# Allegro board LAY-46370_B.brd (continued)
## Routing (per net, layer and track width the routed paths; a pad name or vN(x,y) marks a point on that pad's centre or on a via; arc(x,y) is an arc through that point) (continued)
GND_CHASSIS:
  vias: v1(74.04,7.6) v1(74.04,6.33) v1(74.04,5.06) v1(74.04,3.79) v1(74.13,1.03) v1(75.44,0.95) v1(76.5,0.93) v1(77.77,0.93) v1(79.04,0.93) v1(80.31,0.93) v1(81.19,6.46) v1(81.19,5.19) v1(81.19,3.92) v1(81.19,2.65) v1(81.49,11.08) v1(81.49,9.81) v1(81.58,0.93) v1(82.46,6.46) v1(82.46,5.19) v1(82.46,3.92) v1(82.46,2.65) v1(82.76,11.08) v1(82.76,9.81) v1(82.85,0.93) v1(83.73,6.46) v1(83.73,5.19) v1(83.73,3.92) v1(83.73,2.65) v1(84.03,11.08) v1(84.03,9.81) v1(84.12,0.93) v1(85.39,0.93) v1(86.66,0.93) v1(87.93,0.93) v1(89.2,0.93) v1(90.47,0.93) v1(91.21,6.76) v1(91.21,5.49) v1(91.21,4.22) v1(91.21,2.95) v1(91.74,0.93) v1(92.48,6.76) v1(92.48,5.49) v1(92.48,4.22) v1(92.48,2.95) v1(93.01,0.93) v1(93.75,6.76) v1(93.75,5.49) v1(93.75,4.22) v1(93.75,2.95) v1(94.28,0.93) v1(95.55,0.93) v1(96.82,0.93) v1(98.09,0.93) v1(99.36,0.93) v1(100.44,4.71) v1(100.44,3.44) v1(100.44,2.17) v1(100.63,0.93) v1(101.79,4.68) v1(101.79,3.41) v1(101.79,2.14) v1(101.79,0.9) v1(102.06,10.86) v1(102.06,9.59) v1(102.06,8.32) v1(103.06,4.68) v1(103.06,3.41) v1(103.06,2.14) v1(103.06,0.9) v1(103.41,10.84) v1(103.41,9.57) v1(103.41,8.3) v1(104.33,0.9) v1(104.68,10.84) v1(104.68,9.57) v1(104.68,8.3) v1(105.6,0.9) v1(106.87,0.9) v1(107.06,10.4) v1(107.06,9.13) v1(108.14,0.9) v1(108.4,10.38) v1(108.4,9.11) v1(109.41,0.9) v1(110.68,0.9) v1(111.79,5.91) v1(111.79,3.88) v1(111.79,1.85) v1(112.91,10.65) v1(112.91,9.38) v1(112.91,8.11) v1(113.82,5.91) v1(113.82,3.88) v1(113.82,1.85) v1(114.26,10.62) v1(114.26,9.35) v1(114.26,8.08) v1(115.53,10.62) v1(115.53,9.35) v1(115.53,8.08) v1(115.85,5.91) v1(115.85,3.88) v1(115.85,1.85) v1(117.89,5.91) v1(117.89,3.88) v1(117.89,1.85) v1(119.92,5.91) v1(119.92,3.88) v1(119.92,1.85) v1(121.8,8.92) v1(121.8,7.65) v1(121.95,5.91) v1(121.95,3.88) v1(121.95,1.85) v1(123.14,8.89) v1(123.14,7.62) v1(123.98,5.91) v1(123.98,3.88) v1(123.98,1.85) v1(126.01,5.91) v1(126.01,3.88) v1(126.01,1.85) v1(128.05,5.91) v1(128.05,3.88) v1(128.05,1.85) v1(130.08,5.91) v1(130.08,3.88) v1(130.08,1.85) v1(132.11,5.91) v1(132.11,3.88) v1(132.11,1.85) v1(134.14,5.91) v1(134.14,3.88) v1(134.14,1.85) v1(136.17,5.91) v1(136.17,3.88) v1(136.17,1.85) v1(138.21,5.91) v1(138.21,3.88) v1(138.21,1.85) v1(140.24,5.91) v1(140.24,3.88) v1(140.24,1.85) v1(140.42,10.51) v1(140.42,9.24) v1(140.42,7.97) v1(141.36,10.51) v1(141.36,9.24) v1(141.36,7.97) v1(142.27,5.91) v1(142.27,3.88) v1(142.27,1.85) v1(144.3,5.91) v1(144.3,3.88) v1(144.3,1.85) v1(146.33,5.91) v1(146.33,3.88) v1(146.33,1.85) v1(146.9,10.89) v1(146.9,9.62) v1(146.9,8.35) v1(148.17,10.89) v1(148.17,9.62) v1(148.17,8.35) v1(148.37,5.91) v1(148.37,3.88) v1(148.37,1.85) v1(149.44,10.89) v1(149.44,9.62) v1(149.44,8.35) v1(150.4,5.91) v1(150.4,3.88) v1(150.4,1.85) v1(150.71,10.89) v1(150.71,9.62) v1(150.71,8.35) v1(151.85,5.93) v1(151.85,3.9) v1(151.85,1.87) v1(151.98,10.89) v1(151.98,9.62) v1(151.98,8.35) v1(153.25,10.89) v1(153.25,9.62) v1(153.25,8.35) v1(153.88,5.93) v1(153.88,3.9) v1(153.88,1.87) v1(154.52,10.89) v1(154.52,9.62) v1(154.52,8.35) v1(155.91,5.93) v1(155.91,3.9) v1(155.91,1.87) v1(157.95,5.93) v1(157.95,3.9) v1(157.95,1.87) v1(159.98,5.93) v1(159.98,3.9) v1(159.98,1.87) v1(160.75,7.65) v1(162.02,7.65) v1(162.01,5.93) v1(162.01,3.9) v1(162.01,1.87) v1(164.04,5.93) v1(164.04,3.9) v1(164.04,1.87) v1(166.07,5.93) v1(166.07,3.9) v1(166.07,1.87) v1(168.11,5.93) v1(168.11,3.9) v1(168.11,1.87) v1(170.14,5.93) v1(170.14,3.9) v1(170.14,1.87) v1(172.17,5.93) v1(172.17,3.9) v1(172.17,1.87) v1(174.2,5.93) v1(174.2,3.9) v1(174.2,1.87) v1(176.23,5.93) v1(176.23,3.9) v1(176.23,1.87) v1(178.27,5.93) v1(178.27,3.9) v1(178.27,1.87) v1(179.27,7.77) v1(180.3,5.93) v1(180.3,3.9) v1(180.3,1.87) v1(181.12,7.65) v1(182.33,5.93) v1(182.33,3.9) v1(182.33,1.87) v1(184.36,5.93) v1(184.36,3.9) v1(184.36,1.87) v1(185.35,7.65) v1(185.63,1.75) v1(185.66,10.41)
VBUS_IN:
  vias: v1(20.41,95.25) v1(20.39,93.95) v1(20.39,92.79) v1(21.49,95.25) v1(21.47,93.95) v1(21.47,92.8) v1(29.06,31.77) v1(29.07,31.13) v1(30.18,31.78) v1(30.19,31.14) v1(31.34,31.78) v1(31.35,31.14) v1(32.63,31.76) v1(32.64,31.11) v1(40.18,72.83) v1(40.16,71.54) v1(40.16,70.38) v1(41.38,72.79) v1(41.36,71.49) v1(41.36,70.33)
VBUS_USB_DBG: length 3.8
  TOP w0.381: v1(9.31,8.97) L15.2 v1(8.51,8.2)
  BOTTOM w0.381: C237.1 v1(5.11,10.61) ; C238.1 v1(2.78,10.63) ; C236.1 v1(3.95,10.64)
  vias: v1(28.1,58.96) v1(28.75,58.95)
VCC_3V6: length 10.1
  TOP w0.381: v1(40.5,62.64) 40.75,62.89 v1(47.35,62.89)
  BOTTOM w0.254: C263.1 v1(40.5,62.64) 41.46,63.61 U63.9
  BOTTOM w0.381: R258.1 v1(47.35,62.89)
VCC_FT_1V8: length 25.5
  TOP w0.254: U60.37 v1(14.77,26.15) ; U60.64 v1(8.32,17.7) ; U60.12 v1(14.77,16.74)
  TOP w0.381: L23.2 v1(4.86,35.01) ; R421.1 v1(36.17,65.18)
  BOTTOM w0.203: U7.11 13.43,50.64 12.9,51.18 C306.2
  BOTTOM w0.254: U70.21 8.08,68.82 C319.1 ; v1(19.56,72.23) 19.56,72.83 C335.1 20.26,72.84 20.32,72.78 U66.6 ; TP127.1 22.44,64.38 21.76,65.06 C327.1 21.28,65.07 U67.6
  BOTTOM w0.381: v1(8.07,67.06) C320.1 C319.1 ; C298.1 8.42,17.8 v1(8.32,17.7) ; R416.1 v1(16.96,65.84) ; C299.1 14.77,16.74 v1(14.77,16.74) ; L24.1 v1(6.73,26.01) ; v1(14.77,26.15) 14.79,26.14 C300.1 ; R419.1 v1(11.94,63.63) ; R420.1 v1(8.67,63.64) ; C327.1 v1(20.6,65.06) ; R415.1 v1(16.96,68.65) ; v1(14.6,51.8) C305.1 C306.2 ; R410.1 v1(19.92,69.91) ; R417.1 v1(16.93,64.24) ; R418.1 v1(13.02,63.6)
VCC_FT_3V3: length 44.1
  TOP w0.203: C330.1 14.47,36.27 U61.2
  TOP w0.254: U60.31 v1(17.73,24.7) ; U60.20 v1(17.73,19.2) ; U60.42 v1(12.27,26.15) ; U60.56 v1(8.32,21.7) ; U60.50 v1(8.32,24.7)
  TOP w0.381: R333.1 v1(22.41,21.39) ; R334.1 v1(22.38,22.99) ; L22.1 v1(11.17,11.91) ; U74.3 v1(6.04,28.78) ; R241.2 v1(5.25,25.69) ; R237.2 v1(10.33,34.09) ; v1(2.17,16.06) C239.1 v1(3.74,16.06) ; v1(4.79,28.07) C324.1 4.14,28.09 U74.1 ; v1(11.18,33.98) 11.48,33.68 R235.2 ; R242.2 v1(9.17,34.11) ; C330.1 C331.1 v1(14.55,34.46) ; L21.1 v1(14.89,12.84) ; R236.1 v1(3.84,19.44) ; R240.1 v1(3.85,18.3) ; R329.1 v1(16.83,12.47)
  TOP w0.508: C239.1 2.9,16.01 U59.5
  BOTTOM w0.254: C317.1 8.2,69.82 U70.23 ; C307.1 15.7,50.43 15.25,49.99 U7.1
  BOTTOM w0.381: R411.1 v1(8.06,74.61) ; v1(17.73,24.7) 17.72,24.68 C246.1 ; R413.1 v1(6.06,69.46) ; v1(17.73,19.2) 17.72,19.21 C244.1 ; TP126.1 25.64,47.68 v1(25.67,47.65) C338.1 26.9,48.11 U80.8 ; R440.2 v1(24.4,53.92) ; C317.1 C318.1 v1(8.04,71.66) ; C307.1 16.66,49.39 C308.2 v1(16.67,48.74) ; v1(8.32,24.7) 8.47,24.54 C297.1 9.02,24.52 C243.1 9.02,21.73 C296.1 8.34,21.72 v1(8.32,21.7) ; R385.1 v1(19.25,51.85) ; C245.1 12.29,26.13 v1(12.27,26.15)
VDD_1V8: length 111.5
  TOP w0.203: C55.1 49.26,18.93 49.12,18.8 U18.4 ; C328.1 15.14,36.67 U61.3 ; U4.3 118.13,30.71 C286.1
  TOP w0.254: v1(193.39,33.3) 193.21,33.12 U50.10 ; C228.1 181.91,77.6 U55.1 ; C217.1 137.15,38.14 U53.3 ; U50.8 194.84,31.82 v1(195.11,32.09) ; U79.6 163.85,130.39 C345.1
  TOP w0.305: v1(181.37,88.13) 181.65,87.85 U1.23 ; U57.1 181.75,59.95 C232.1 ; C230.1 181.96,95.65 U56.1 ; C234.1 181.78,51.53 U58.1 ; U2.6 178.32,90.69 C5.1 178.85,90.73 v1(178.9,90.77) ; C10.1 179.25,103.27 U5.1 ; 16.22,32.09 U78.6 ; U54.9 131.06,58.33 131.38,58.65 C336.1 ; U54.12 129.56,58.18 129.4,58.35 C337.1
  TOP w0.33: J13.A5 v1(88.85,133.56) ; J16.A5 v1(112.84,133.56) ; J15.A6 v1(136.04,133.56) ; J13.A6 v1(88.05,133.56) ; J14.A5 v1(40.86,133.56) ; J16.A6 v1(112.04,133.56) ; J15.A5 v1(136.84,133.56) ; J12.A5 v1(64.86,133.56) ; J14.A6 v1(40.06,133.56) ; J12.A6 v1(64.06,133.56)
  TOP w0.381: R226.1 v1(182.47,53.29) ; C228.1 v1(180.84,78.04) ; L10.1 v1(157.08,114.99) ; C10.1 v1(177.99,103.84) ; v1(161.14,124.63) R178.1 161.14,125.26 R177.1 ; TP123.1 87.37,115.48 v1(87.81,115.92) ; v1(14.71,40.11) 15.01,39.81 R429.1 ; R147.1 v1(167.25,112.27) ; R284.2 v1(6.36,136.33) ; U48.1 164.2,127.2 C168.1 163.84,128.66 C169.1 v1(163.84,129.4) ; 16.22,32.09 15.5,32.09 C346.1 15.5,32.53 v1(15.72,32.76) ; R312.1 v1(121.96,30.89) ; L9.2 v1(167.48,111.06) ; v1(175.49,102.82) 175.66,102.65 R7.1 176.2,102.62 R8.1 ; R130.1 v1(162.19,114.78) ; v1(136.69,39.49) C218.2 137.37,39.48 C217.1 ; C234.1 v1(180.73,51.94) ; v1(120.31,30.12) 120.11,30.32 C287.1 119.61,30.31 C286.1 ; C232.1 v1(180.35,60.71) ; v1(164.45,129.95) 163.95,130.46 C345.1 ; R244.1 v1(15.4,126.96) ; Q5.1 v1(163.83,134.02) ; R243.1 v1(15.41,125.86) ; R286.2 v1(9.31,136.33) ; v1(14.56,37.72) C329.1 C328.1 ; R283.2 v1(4.89,136.33) ; R224.1 v1(182.43,97.03) ; R15.1 v1(179.79,105.2) ; C55.1 C56.1 47.73,19.35 v1(47.47,19.62) ; R285.2 v1(7.83,136.33) ; R43.2 v1(24.23,26.2) ; R225.1 182.04,61.84 v1(182.39,62.19) ; R246.1 v1(24.09,127.95) ; R223.1 v1(182.58,79.41) ; TP132.1 v1(93.56,54.24) ; C230.1 v1(181.18,95.78) ; R70.1 v1(108.41,25.64) ; R431.1 v1(19.77,31.32) ; C337.1 v1(128.76,59.36) ; R101.1 v1(87.25,37.56) ; C336.1 v1(132.03,59.37) ; D22.A v1(12.62,128.89) ; R10.1 v1(176.2,98.73) ; R216.1 v1(136.53,42.24) ; R186.1 v1(165.75,131.05) ; R9.1 v1(175.59,100.47)
  BOTTOM w0.203: U20.14 11.97,78.37 11.98,78.38 C321.1 ; C309.1 8.04,50.58 U8.14
  BOTTOM w0.254: C12.1 109.61,94.42 U6.1 ; C37.1 111.57,85.28 U52.12 ; C33.1 109.84,85.46 110.07,85.22 U52.9
  BOTTOM w0.305: U3.1 C7.1
  BOTTOM w0.381: v1(114.13,98.12) 113.97,97.96 R19.1 ; C33.1 v1(109.1,86.25) ; R41.1 v1(127.84,84.3) ; v1(9.83,51.8) C310.2 C309.1 ; v1(131.92,82.95) C6.1 131.92,82.23 C7.1 ; v1(151.67,85.68) R422.2 R423.2 ; R18.1 v1(112.78,98.12) ; v1(193.39,33.3) 193.38,33.29 C185.1 C186.1 ; R16.1 v1(110.01,98.1) ; v1(12.76,76.68) C322.2 C321.1 ; C1.1 181.6,87.3 C2.1 181.61,87.89 v1(181.37,88.13) ; R27.1 v1(107.85,93.75) ; R313.2 v1(83.88,112.8) ; R4.1 v1(127.82,83.23) ; R17.1 v1(111.18,98.11) ; C184.1 195.02,32 v1(195.11,32.09) ; C12.1 v1(109.21,95.46) ; C37.1 v1(113.2,86.26)
  vias: v1(95.13,59.34) v1(95.13,58.73) v1(95.74,59.34) v1(95.74,58.73)
VDD_3V3: length 53.9
  TOP w0.203: U4.2 117.73,30.61 C289.1 ; U5.11 180.6,103.56 C11.1 ; C54.1 48.5,26.73 U17.3
  TOP w0.254: C30.1 35.5,18.32 U11.3 ; C219.1 136.97,37.74 U53.2
  TOP w0.305: v1(182.7,87.96) 182.65,87.91 U1.21 ; v1(68.17,31.9) 68.13,31.9 67.06,32.97 R48.1 ; R448.1 v1(56.68,26.48)
  TOP w0.381: C289.1 116.33,30.31 C288.1 v1(116.32,30.91) ; R113.2 88.18,23.71 v1(87.94,23.94) ; v1(48.27,25.67) 48.62,26.02 C54.1 ; v1(93.6,37.54) 93.6,36.82 L1.1 93.73,36.91 R84.2 ; R447.2 27.93,18.2 v1(27.76,18.37) ; R212.1 v1(139.3,23.48) ; v1(79.63,22.58) 79.92,22.88 L6.1 ; v1(169.75,131.66) D9.A 170.57,132.62 v1(170.54,132.65) ; R14.1 v1(183.62,99.35) ; C11.1 v1(181.52,103.84) ; L14.1 v1(199.28,22.68) ; C30.1 35.44,18.87 v1(34.87,18.87) ; v1(82.32,114.3) 82.18,114.17 R66.1 ; R60.1 v1(39.83,28.04) ; L5.1 v1(75.33,36.98) ; R68.1 v1(58.9,26.46) ; R426.1 v1(131.2,23.48) ; R12.1 v1(183.64,101.51) ; U51.11 134.6,24.93 v1(134.64,24.89) ; R11.1 v1(183.67,102.57) ; TP131.1 v1(90.19,54.24) ; R83.2 v1(107.76,25.16) ; R270.1 v1(4.2,140.76) ; R129.1 v1(163.9,114.18) ; v1(136.78,36.24) C220.2 137.37,36.25 C219.1 ; L2.1 v1(98.5,23) ; R114.2 v1(74.85,35.19) ; R13.1 v1(183.6,100.43)
  BOTTOM w0.254: U6.11 109.64,93.07 C13.1 ; C9.1 136.68,83.93 U3.23 ; R20.1 v1(109.94,90.02)
  BOTTOM w0.305: U3.24 134.49,82.49 C8.1
  BOTTOM w0.381: R269.1 45.59,107.03 v1(45.95,106.66) ; C204.1 135.1,25.67 C205.1 135.11,25.36 v1(134.64,24.89) ; C8.1 v1(135.45,82.23) ; v1(136.53,83.19) 136.78,83.45 C9.1 ; R282.1 v1(17.92,99.45) ; R23.1 v1(114.62,90.64) ; R22.1 v1(111.96,90.64) 111.96,90.64 R21.1 ; C13.1 v1(109.22,92.01) ; C4.1 183.77,87.28 C3.1 v1(182.7,87.96) ; R264.1 v1(50.72,101.8)
  vias: v1(95.28,64.71) v1(95.29,64.1) v1(95.89,64.71) v1(95.9,64.1)
VDD_3V3_CN: length 1.7
  TOP w0.254: D9.C 170.51,134.14
  TOP w0.381: 170.51,134.14 R174.1
VDD_5V: length 90.9
  TOP w0.203: U17.12 42.29,26.33 C57.2 ; U11.12 29.98,17.92 C31.2
  TOP w0.33: J12.A16 v1(56.06,133.56) ; J13.A16 v1(80.05,133.56) ; J16.A17 v1(103.24,133.56) ; J15.A16 v1(128.04,133.56) ; J12.A17 v1(55.26,133.56) ; J14.A16 v1(32.06,133.56) ; J16.A16 v1(104.04,133.56) ; J15.A17 v1(127.24,133.56) ; J13.A17 v1(79.25,133.56) ; J14.A17 v1(31.26,133.56)
  TOP w0.381: R204.1 v1(182.11,21.02) ; R46.1 v1(71.08,40.15) ; U51.3 135.87,32.47 v1(136.18,32.78) ; v1(181.72,126.45) 176.59,126.45 176.33,126.19 R455.1 176.06,125.27 Q16.2 ; v1(185.34,21.41) Q6.2 v1(184.52,20.67) ; C197.1 v1(183.23,21.02) ; C31.2 29.28,16.98 29.81,16.98 v1(29.98,17.14) ; C57.2 v1(42.21,25.59)
  L6_IN2 w0.381: v1(42.21,25.59) 33.64,25.59 30.37,22.31 30.37,17.53 v1(29.98,17.14)
  BOTTOM w0.381: v1(136.18,32.78) 136.5,32.46 C202.1 135.41,32.13 C203.1 ; v1(73.77,37.64) 69.15,33.02 69.15,30.23 63.5,24.58 56.86,24.58 55.39,23.12 45.56,23.12 43.1,25.59 v1(42.21,25.59)
  vias: v1(55.45,103.16) v1(55.46,104.44) v1(55.47,103.81) v1(56.2,104.47) v1(56.21,103.84) v1(56.22,103.17) v1(68.27,40.01) v1(68.26,39.37) v1(195.65,109.24) v1(195.65,108.61) v1(195.66,107.95) v1(197.97,109.14) v1(197.98,108.51) v1(197.99,107.85) v1(199.99,106.73) v1(200,106.1) v1(200.01,105.45)
1GB_LINK/ACTIVE: length 20.2
  TOP w0.254: R78.1 95.45,19.19 95.45,13.24 99.43,9.25 99.43,6.17 J8.11
10M_100M_LINK/ACTIVE: length 18.5
  TOP w0.254: R74.1 108.18,14.81 107,13.64 107,12.53 105.59,11.11 105.59,3.64 J8.13
AUD_3V3: length 8.2
  TOP w0.305: L14.2 199.15,24.26 R187.1 197.8,24.57 C189.1 196.49,24.26 C190.1 195.53,25.59 193.71,27.4 U50.32
AUD_5V: length 7.1
  TOP w0.203: U50.26 v1(190.71,26.94) ; v1(188.65,29.78) 188.69,29.82 U50.21
  TOP w0.381: v1(187.33,22.06) Q6.3 185.95,22.53 C15.1
  BOTTOM w0.381: v1(188.65,29.78) 188.75,29.68 C188.1
  BOTTOM w0.508: v1(190.71,26.94) 190.43,27.22 C187.1
AUD_NINT: length 95.2
  TOP w0.102: v1(112,66.94) 112.03,66.94 112.09,67 J4.26
  TOP w0.109: v1(191.12,37.61) 190.17,36.66 R188.1
  BOTTOM w0.109: v1(191.12,37.61) 190.93,37.61 182.57,45.96 148.15,45.96 127.47,66.65 112.27,66.65 112,66.92 v1(112,66.94)
AUD_PWR_EN: length 114.3
  TOP w0.102: J4.24 112.27,66.6 112.17,66.51 111.76,66.51 110.89,67.38 v1(110.89,67.94)
  TOP w0.203: R207.1 v1(186.49,20.13)
  L6_IN2 w0.114: v1(186.49,20.13) v1(186.49,45.33)
  BOTTOM w0.109: v1(110.89,67.94) 110.89,68.06 111.25,68.42 127.95,68.42 149.02,47.35 184.46,47.35 v1(186.49,45.33)
AUD_SCL: length 2.9
  TOP w0.203: U50.17 189.18,31.82 188.9,32.1 187.77,32.1 R198.2
AUD_SDA: length 2.6
  TOP w0.203: U50.18 189.12,31.32 188.74,31.71 R197.2
BOOT_MODE0: length 88.6
  TOP w0.109: v1(10.24,76.59) 8.12,76.59 7.06,77.64 7.06,79.54 9.99,82.46 55.95,82.46 71.39,97.89 71.39,105.49 72.69,106.79 J1.9
  BOTTOM w0.109: v1(10.24,76.59) 9.97,76.86 U20.2
BOOT_MODE1: length 86
  TOP w0.109: v1(8.56,77.03) 8.11,77.03 7.34,77.81 7.34,79.31 10.2,82.18 56.15,82.18 72.03,98.07 72.03,105.8 73.09,106.86 J1.11
  BOTTOM w0.109: U20.5 v1(8.56,77.03)
BOOT_MODE2: length 83.9
  TOP w0.109: v1(7.84,78.73) 7.84,79.36 10.26,81.78 56.33,81.78 72.62,98.07 72.62,106.05 73.36,106.8 73.36,107.09 73.49,107.22 J1.13
  BOTTOM w0.109: v1(7.84,78.73) 8.2,78.37 U20.7
BOOT_MODE3: length 82.1
  TOP w0.109: v1(10.02,80.62) 10.78,81.38 56.44,81.38 72.86,97.79 72.86,105.96 73.6,106.7 73.6,106.91 73.89,107.2 J1.15
  BOTTOM w0.109: U20.10 9.57,79.49 9.5,79.56 9.5,80.11 v1(10.02,80.62)
BYPASS: length 2.3
  TOP w0.109: C29.2 35.15,19.84 34.03,18.72 U11.4
BYPASS1: length 1.4
  TOP w0.203: U17.4 46.97,27.13 C51.2
CAN1/I2C5_SEL: length 81.4
  TOP w0.109: v1(129.7,81.21) 130.01,81.52 156.4,81.52 159.6,84.71 178.89,84.71 179.16,84.98 R444.1 179.34,85.47 U1.3
  L6_IN2 w0.114: v1(108.51,84.9) 109.2,85.58 v1(110.45,85.58)
  BOTTOM w0.102: U52.10 110.57,85.48 110.47,85.58 v1(110.45,85.58) ; U52.7 109.06,84.9 v1(108.51,84.9)
  BOTTOM w0.109: v1(108.51,84.9) 108.14,84.52 108.14,82.79 110.02,80.91 121.78,80.91 122.64,81.78 129.13,81.78 v1(129.7,81.21)
CAN1_H: length 14
  TOP w0.254: J19.7 132.88,12.73 134,13.85 D14.2 134.19,17.16 L19.2 132.66,19 C206.2 131.32,18.98 R210.1
CAN1_L: length 11.7
  TOP w0.254: R211.1 138.58,18.99 C208.1 137.2,19 L19.3 135.64,17.21 D14.1 136.22,16.63 136.22,13.25 J19.2
CAN1_RX: length 70.4
  TOP w0.109: U53.8 133.3,39.15 132.01,40.44 v1(132.01,40.56) 132.01,41.4 TP108.1
  L6_IN2 w0.114: v1(129.69,81.85) 133.21,78.32 133.21,41.76 v1(132.01,40.56)
  BOTTOM w0.109: U52.5 109.57,83.21 109.33,82.97 109.33,82.03 110.06,81.3 121.49,81.3 122.3,82.11 129.43,82.11 v1(129.69,81.85)
CAN1_RX_3V3: length 5.4
  TOP w0.254: U51.4 v1(134.6,32.72) ; U53.13 134.34,36.2 v1(134.13,35.98)
  L6_IN2 w0.254: v1(134.13,35.98) 134.13,33.2 v1(134.6,32.72)
CAN1_STBY_3V3: length 66.6
  TOP w0.109: R212.2 138.41,24.48 U51.14 v1(138.41,27.37)
  L6_IN2 w0.114: v1(137.17,88.39) 137.17,86.62 138.21,85.58 138.21,27.58 v1(138.41,27.37)
  BOTTOM w0.102: U3.15 136.71,87.93 v1(137.17,88.39)
CAN1_TX: length 66.7
  TOP w0.102: U53.6 135.14,39.84 v1(134.8,40.19)
  TOP w0.109: TP106.1 133.88,41.1 v1(134.8,40.19)
  L6_IN2 w0.114: v1(134.8,40.19) 133.51,41.47 133.51,78.65 129.67,82.5 v1(129.65,82.5)
  BOTTOM w0.109: v1(129.65,82.5) 121.47,82.5 120.55,83.41 111.55,83.41 111.07,83.89 U52.2
CAN1_TX_3V3: length 6.5
  TOP w0.254: U51.1 138.41,32.13 135.14,35.4 U53.15
CAN1H: length 8.5
  TOP w0.254: U51.13 137.14,21.84 136.32,21.01 134.45,21.01 134.19,21.28 L19.1
CAN1L: length 4.2
  TOP w0.254: L19.4 135.87,22.28 U51.12
CAN2_H: length 18.3
  TOP w0.254: R214.1 162.21,20.08 C214.2 163.59,20.1 L20.2 165.15,18.22 D15.2 165.01,15.29 166.38,13.92 167.23,13.92 169.16,11.98 169.16,10.74 171.46,8.44 J20.7
CAN2_L: length 15.3
  TOP w0.254: J20.2 171.74,12.85 170.36,12.85 166.89,16.32 D15.1 166.89,18.75 166.6,19.03 L20.3 168.14,20.1 C216.1 169.53,20.11 R215.1
CAN2_RX: length 36.6
  TOP w0.109: U53.9 131.06,38.54 TP109.1 112.02,57.58 112.02,63.03 112.39,63.41 J4.8
CAN2_RX_3V3: length 7.5
  TOP w0.254: U51.7 130.79,34.3 133.84,37.34 U53.12
CAN2_STBY_3V3: length 68.7
  TOP w0.109: R426.2 130.79,24.53 U51.8 v1(130.79,27.62)
  L6_IN2 w0.114: v1(130.79,27.62) 130.79,28.23 137.81,35.24 137.81,85.48 136.49,86.8 v1(136.49,88.43)
  BOTTOM w0.102: U3.14 v1(136.49,88.43)
CAN2_TX: length 25.3
  TOP w0.102: v1(130.27,58.7) 130.06,58.5 U54.11
  TOP w0.109: U53.7 134.74,39.54 132.96,41.32 132.96,42.09 v1(132.66,42.39) 131.03,42.39 TP107.1
  L6_IN2 w0.127: v1(132.66,42.39) 130.27,44.78 v1(130.27,58.7)
CAN2_TX_3V3: length 6.2
  TOP w0.254: U53.14 134.74,35.2 132.06,32.52 U51.6
CAN2H: length 38.4
  TOP w0.254: L20.1 165.6,23.59 165.6,26.36 163.91,28.04 133.52,28.04 132.99,27.51 132.99,26.97 133.33,26.62 U51.10
CAN2L: length 40.3
  TOP w0.254: U51.9 132.06,26.61 132.43,26.97 132.43,27.74 133.29,28.6 164.15,28.6 166.16,26.59 166.16,23.59 L20.4
CLK_PD#: length 3.2
  TOP w0.109: U29.22 160.2,106.43 TP128.1
CLKIN1: length 7.3
  TOP w0.102: TP1.1 110.43,116.55 112.1,114.89 112.1,113.26 111.26,112.43 111.26,111.42 111.53,111.15 J2.86
CLKIN2: length 6
  TOP w0.102: TP3.1 113.21,116.49 113.21,111.06 113.13,110.98 J2.94
CLKOUT1: length 6.4
  TOP w0.102: J2.90 112.33,111.16 112.23,111.27 112.23,111.92 112.53,112.23 112.53,115.77 TP2.1
CLKOUT2: length 6.3
  TOP w0.102: TP4.1 114.08,115.84 114.08,111.22 113.93,111.07 J2.98
CON_JTAG_TCK: length 87.1
  L6_IN2 w0.114: J24.4 17.79,128.58 17.21,128.01 17.21,100.51 5.14,88.44 5.14,54.81 v1(9.31,50.64)
  BOTTOM w0.109: U8.16 9.25,50.58 v1(9.31,50.64)
CON_JTAG_TDI: length 105
  TOP w0.109: J24.8 17.94,131.12 17.53,130.71 17.53,127.73 R244.2
  L6_IN2 w0.114: J24.8 17.02,131.12 16.29,130.39 16.29,100.9 4.47,89.07 4.47,49.84 6.77,47.53 7.77,47.53 9.78,49.53 10.16,49.53 v1(10.59,49.97)
  BOTTOM w0.109: U8.3 9.79,49.17 v1(10.59,49.97)
CON_JTAG_TDO: length 88.9
  L6_IN2 w0.114: J24.6 17.26,129.85 16.77,129.36 16.77,100.7 4.77,88.7 4.77,51.71 v1(6.51,49.97)
  BOTTOM w0.109: U8.12 v1(6.51,49.97)
CON_JTAG_TMS: length 93.6
  TOP w0.109: J24.2 18.23,127.31 R243.2
  L6_IN2 w0.114: J24.2 18.31,127.31 17.53,126.53 17.53,100.38 5.44,88.3 5.44,57.88 10.32,53 10.32,51.01 7.28,47.98 v1(7.08,47.98)
  BOTTOM w0.109: v1(7.08,47.98) 7.08,48.67 7.18,48.77 U8.9
CSI1_CKN: length 52.4
  TOP w0.091: J1.84 87.5,110.66 87.5,111.2 87.56,111.26 87.56,111.86 88.28,112.58 v1(88.28,112.58) ; J12.A2 67.26,133.05 66.99,133.31 66.99,133.69 67.08,133.78 68.36,133.78 69.95,132.19 69.95,127.09 69.86,126.99 U31.10 U31.1 69.86,125.07 69.97,124.95 69.97,124.45 69.81,124.29 v1(69.81,124.22)
  L3_IN1 w0.084: v1(69.81,124.22) 69.97,124.38 69.97,124.75 70.22,124.99 72.52,124.99 73.07,124.45 73.07,122.1 72.82,121.86 70.65,121.86 70.57,121.77 70.57,121.27 70.65,121.18 72.52,121.18 72.87,120.82 72.87,120.36 72.53,120.02 70.65,120.02 70.57,119.93 70.57,119.3 70.74,119.13 82.69,119.13 87.83,113.99 87.83,112.67 87.92,112.58 v1(88.28,112.58)
CSI1_CKP: length 52.5
  TOP w0.091: v1(88.3,112) 88.07,112 87.83,111.75 87.83,111.26 87.9,111.2 87.9,110.66 J1.86 ; v1(70.4,124.22) 70.4,124.29 70.24,124.45 70.24,124.95 70.36,125.07 U31.2 U31.9 70.36,127.01 70.22,127.15 70.22,132.3 68.48,134.05 66.97,134.05 66.72,133.8 66.72,133.32 66.46,133.05 J12.A3
  L3_IN1 w0.084: v1(70.4,124.22) 70.24,124.38 70.24,124.64 70.33,124.73 72.41,124.73 72.8,124.34 72.8,122.21 72.71,122.13 70.54,122.13 70.3,121.88 70.3,121.16 70.54,120.91 72.41,120.91 72.6,120.71 72.6,120.47 72.42,120.29 70.54,120.29 70.3,120.04 70.3,119.19 70.63,118.86 82.58,118.86 87.56,113.88 87.56,112.56 87.81,112.31 87.94,112.31 88.26,112 v1(88.3,112)
CSI1_DN0: length 51.6
  TOP w0.091: v1(85.87,112.6) 85.82,112.6 85.16,111.93 85.16,111.1 85.1,111.03 85.1,110.66 J1.72 ; J12.B2 67.66,128.92 67.39,128.65 67.39,128.14 66.65,127.4 66.65,127.2 66.77,127.09 U32.1 U32.10 66.77,125.07 66.65,124.95 66.65,122.8 v1(66.81,122.64)
  L3_IN1 w0.084: v1(66.81,122.64) 66.65,122.48 66.65,121.56 66.4,121.31 64.18,121.31 64.1,121.23 64.1,121.05 64.18,120.96 66.4,120.96 66.65,120.71 66.65,120.31 66.4,120.07 64.18,120.07 64.1,119.98 64.1,119.8 64.18,119.71 66.4,119.71 66.65,119.47 66.65,119.07 66.4,118.83 64.18,118.83 64.1,118.74 64.1,118.56 64.18,118.47 66.4,118.47 66.65,118.22 66.65,116.66 67.34,115.97 83.04,115.97 85.46,113.54 85.46,112.74 85.67,112.53 85.8,112.53 v1(85.87,112.6)
CSI1_DN1: length 51.3
  TOP w0.091: J12.B5 65.26,128.87 64.99,128.6 64.99,127.94 65.14,127.79 65.14,127.21 65.27,127.09 U32.4 U32.7 65.27,125.07 65.15,124.95 65.15,124.68 v1(65.32,124.5) ; J1.78 86.3,110.66 86.3,111.2 86.36,111.26 86.36,111.87 87.02,112.53 87.04,112.53 v1(87.07,112.56)
  L3_IN1 w0.084: v1(65.32,124.5) 65.16,124.34 65.16,124.08 65.57,123.68 67.47,123.68 68.83,122.32 68.83,117.84 69.67,117 70.49,117 70.57,117.08 70.57,117.55 70.82,117.79 71.22,117.79 71.46,117.55 71.46,117.08 71.55,117 71.73,117 71.82,117.08 71.82,117.68 72.06,117.93 72.46,117.93 72.71,117.68 72.71,117.08 72.8,117 72.97,117 73.06,117.08 73.06,117.68 73.31,117.93 73.71,117.93 73.95,117.68 73.95,117.08 74.04,117 74.22,117 74.31,117.08 74.31,117.68 74.55,117.93 74.95,117.93 75.2,117.68 75.2,117.08 75.29,117 75.46,117 75.55,117.08 75.55,117.68 75.8,117.93 76.2,117.93 76.44,117.68 76.44,117.08 76.53,117 76.71,117 76.8,117.08 76.8,117.68 77.04,117.93 77.44,117.93 77.69,117.68 77.69,117.08 77.78,117 77.95,117 78.04,117.08 78.04,117.68 78.29,117.93 78.69,117.93 78.93,117.68 78.93,117.08 79.02,117 79.2,117 79.29,117.08 79.29,117.68 79.53,117.93 79.93,117.93 80.18,117.68 80.18,117.08 80.26,117 80.44,117 80.53,117.08 80.53,117.68 80.78,117.93 81.17,117.93 81.42,117.68 81.42,117.08 81.51,117 83.44,117 86.61,113.83 86.61,112.73 86.78,112.56 v1(87.07,112.56)
CSI1_DN2: length 51.2
  TOP w0.091: v1(89.47,112.58) 89.47,112.58 88.76,111.87 88.76,111.26 88.7,111.2 88.7,110.66 J1.90 ; v1(58.14,124.47) 58.02,124.59 58.02,125 58.14,125.11 U33.10 U33.1 58.14,127.09 58.02,127.2 58.02,127.4 58.59,127.97 58.59,128.62 58.86,128.89 J12.B13
  L3_IN1 w0.084: v1(58.14,124.47) 57.94,124.28 57.94,123.98 58.21,123.72 58.45,123.72 58.69,123.47 58.69,122.69 58.78,122.6 58.96,122.6 59.05,122.69 59.05,123.47 59.29,123.72 59.69,123.72 59.94,123.47 59.94,122.69 60.03,122.6 60.2,122.6 60.29,122.69 60.29,123.47 60.54,123.72 61.58,123.72 63.77,125.9 73.14,125.9 78.86,120.18 82.88,120.18 89.03,114.03 89.03,112.67 89.12,112.58 v1(89.47,112.58)
CSI1_DN3: length 51.2
  TOP w0.091: J12.B16 56.46,129.15 56.18,128.87 56.18,128.25 56.52,127.9 56.52,126.94 56.64,126.82 U33.4 U33.7 56.64,125.3 56.5,125.16 56.5,124.71 v1(56.66,124.54) ; J1.96 89.89,110.95 89.99,111.05 89.99,111.66 90.29,111.96 90.29,112.23 90.23,112.29 90.15,112.29 90.07,112.37 90.07,112.52 90.16,112.61 v1(90.7,112.61)
  L3_IN1 w0.084: v1(90.7,112.61) 90.94,112.61 91.12,112.78 91.12,113.37 83.65,120.84 79.34,120.84 73.65,126.52 57.55,126.52 56.35,125.32 56.35,124.88 56.66,124.56 v1(56.66,124.54)
CSI1_DP0: length 51.6
  TOP w0.091: v1(66.22,122.64) 66.38,122.8 66.38,124.95 66.27,125.07 U32.9 U32.2 66.27,127.09 66.38,127.2 66.38,127.51 67.12,128.25 67.12,128.66 66.86,128.92 J12.B3 ; v1(85.88,112.01) 85.68,112.01 85.44,111.78 85.44,111.25 85.5,111.2 85.5,110.66 J1.74
  L3_IN1 w0.084: v1(66.22,122.64) 66.38,122.48 66.38,121.67 66.29,121.58 64.07,121.58 63.83,121.34 63.83,120.94 64.07,120.69 66.29,120.69 66.38,120.6 66.38,120.43 66.29,120.34 64.07,120.34 63.83,120.09 63.83,119.69 64.07,119.45 66.29,119.45 66.38,119.36 66.38,119.18 66.29,119.09 64.07,119.09 63.83,118.85 63.83,118.45 64.07,118.2 66.29,118.2 66.38,118.11 66.38,116.55 67.23,115.7 82.93,115.7 85.19,113.43 85.19,112.63 85.81,112.01 v1(85.88,112.01)
CSI1_DP1: length 51.2
  TOP w0.091: J1.80 86.7,110.66 86.7,111.2 86.63,111.26 86.63,111.69 86.91,111.98 v1(87.08,111.98) ; J12.B6 64.46,128.85 64.72,128.58 64.72,127.83 64.88,127.68 64.88,127.2 64.77,127.09 U32.5 U32.6 64.77,125.07 64.88,124.95 64.88,124.65 v1(64.74,124.5)
  L3_IN1 w0.084: v1(64.74,124.5) 64.9,124.34 64.9,123.97 65.46,123.41 67.36,123.41 68.56,122.21 68.56,117.73 69.56,116.73 70.6,116.73 70.84,116.97 70.84,117.44 70.93,117.53 71.11,117.53 71.2,117.44 71.2,116.97 71.44,116.73 71.84,116.73 72.09,116.97 72.09,117.57 72.17,117.66 72.35,117.66 72.44,117.57 72.44,116.97 72.69,116.73 73.08,116.73 73.33,116.97 73.33,117.57 73.42,117.66 73.6,117.66 73.69,117.57 73.69,116.97 73.93,116.73 74.33,116.73 74.57,116.97 74.57,117.57 74.66,117.66 74.84,117.66 74.93,117.57 74.93,116.97 75.18,116.73 75.57,116.73 75.82,116.97 75.82,117.57 75.91,117.66 76.09,117.66 76.17,117.57 76.17,116.97 76.42,116.73 76.82,116.73 77.06,116.97 77.06,117.57 77.15,117.66 77.33,117.66 77.42,117.57 77.42,116.97 77.66,116.73 78.06,116.73 78.31,116.97 78.31,117.57 78.4,117.66 78.58,117.66 78.66,117.57 78.66,116.97 78.91,116.73 79.31,116.73 79.55,116.97 79.55,117.57 79.64,117.66 79.82,117.66 79.91,117.57 79.91,116.97 80.15,116.73 80.55,116.73 80.8,116.97 80.8,117.57 80.89,117.66 81.06,117.66 81.15,117.57 81.15,116.97 81.4,116.73 83.33,116.73 86.34,113.71 86.34,112.62 86.82,112.14 86.94,112.14 87.07,112.02 87.07,111.98 v1(87.08,111.98)
CSI1_DP2: length 51.2
  TOP w0.091: J1.92 89.1,110.66 89.1,111.2 89.03,111.26 89.03,111.7 89.33,112 v1(89.49,112) ; J12.B14 58.06,128.87 58.32,128.6 58.32,128.08 57.75,127.51 57.75,127.2 57.64,127.09 U33.2 U33.9 57.64,125.07 57.75,124.95 57.75,124.67 v1(57.55,124.47)
  L3_IN1 w0.084: v1(57.55,124.47) 57.68,124.35 57.68,123.87 58.1,123.45 58.34,123.45 58.43,123.36 58.43,122.58 58.67,122.33 59.07,122.33 59.31,122.58 59.31,123.36 59.4,123.45 59.58,123.45 59.67,123.36 59.67,122.58 59.92,122.33 60.31,122.33 60.56,122.58 60.56,123.36 60.65,123.45 61.7,123.45 63.88,125.64 73.03,125.64 78.75,119.91 82.77,119.91 88.76,113.92 88.76,112.56 89.32,112 v1(89.49,112)
CSI1_DP3: length 51.2
  TOP w0.091: v1(90.74,112.02) 90.26,111.55 90.26,111.18 90.29,111.16 J1.98 ; J12.B17 55.66,129.13 55.91,128.87 55.91,128.14 56.25,127.79 56.25,126.93 56.14,126.81 U33.5 U33.6 56.14,125.34 56.23,125.24 56.23,124.69 v1(56.08,124.54)
  L3_IN1 w0.084: v1(56.08,124.54) 56.08,125.43 57.44,126.79 73.76,126.79 79.45,121.11 83.76,121.11 91.38,113.48 91.38,112.67 91.05,112.34 v1(90.74,112.02)
CSI1_I2C_SCL: length 3.3
  TOP w0.102: J12.B11 60.46,126.55 R162.1
CSI1_I2C_SDA: length 3.4
  TOP w0.102: R160.1 61.26,126.69 J12.B10
CSI1_SYNC: length 39.8
  TOP w0.102: J1.21 75.09,106.85 74.75,106.51 74.75,105.92 74.62,105.79 73.93,105.79 v1(73.64,106.08)
  L6_IN2 w0.114: v1(60.3,136.3) 62.48,134.12 62.48,120.54 70.83,112.19 70.83,108.68 73.43,106.08 v1(73.64,106.08)
  BOTTOM w0.109: v1(60.3,136.3) 60.28,136.28 R28.1
CSI2_CKN: length 35.3
  TOP w0.091: v1(97.12,111.97) 97.25,112.1 97.38,112.1 97.6,111.88 97.6,111.29 97.53,111.22 J2.16 ; v1(92.24,120.72) 92.24,120.7 91.92,120.38 91.92,120.18 92.23,119.87 93.56,119.87 93.96,120.27 93.96,125.12 93.73,125.36 U34.1 U34.10 93.73,126.85 93.96,127.08 93.96,132.45 92.4,134.01 92.15,134.01 92.06,133.92 92.06,133.46 91.97,133.37 91.74,133.37 91.65,133.46 91.65,133.92 91.55,134.01 91.22,134.01 90.93,133.72 90.93,133.36 91.25,133.04 J13.A2
  L3_IN1 w0.084: v1(97.12,111.97) 97.35,112.2 97.36,112.2 97.79,112.63 97.79,114.2 91.91,120.09 91.91,120.37 92.24,120.7 v1(92.24,120.72)
CSI2_CKP: length 35.4
  TOP w0.091: v1(97.12,112.55) 97.3,112.55 97.87,111.99 97.87,111.29 97.93,111.22 J2.18 ; J13.A3 90.45,133.03 90.66,133.25 90.66,133.83 91.11,134.28 92.51,134.28 94.23,132.56 U34.9 U34.2 94.23,120.16 93.67,119.6 92.12,119.6 91.65,120.07 v1(91.65,120.72)
  L3_IN1 w0.084: v1(91.65,120.72) 91.64,120.71 91.64,119.98 97.53,114.09 97.53,112.74 97.34,112.55 v1(97.12,112.55)
CSI2_DN0: length 32.9
  TOP w0.091: v1(90.74,124.48) 90.58,124.64 90.58,125.2 90.71,125.32 U35.10 U35.1 90.71,126.85 90.47,127.08 90.47,127.34 91.38,128.24 91.38,128.67 91.65,128.94 J13.B2 ; J2.28 99.93,111.22 100,111.29 100,111.73 99.76,111.97 v1(99.54,111.97)
  L3_IN1 w0.084: v1(99.54,111.97) 99.69,112.13 99.98,112.13 100.22,112.38 100.22,118.66 99.58,119.31 99.11,119.31 98.77,118.98 98.65,118.98 98.52,119.1 98.52,119.23 98.92,119.62 98.92,119.97 98.64,120.25 98.29,120.25 97.89,119.86 97.77,119.86 97.64,119.98 97.64,120.11 98.04,120.5 98.04,120.85 97.75,121.13 97.41,121.13 97.01,120.74 96.89,120.74 96.76,120.86 96.76,120.99 97.16,121.38 97.16,121.73 96.87,122.01 96.53,122.01 96.13,121.62 96.01,121.62 95.88,121.74 95.88,121.87 96.14,122.13 96.14,122.74 95.4,123.49 90.67,123.49 90.55,123.62 90.55,124.28 v1(90.74,124.48)
CSI2_DN1: length 32.8
  TOP w0.091: v1(89.26,124.51) 89.09,124.68 89.09,124.95 89.21,125.07 U35.7 U35.4 89.21,127.05 89.09,127.17 89.09,127.86 88.98,127.96 88.98,128.74 89.25,129.01 J13.B5 ; J2.22 98.73,111.22 98.8,111.29 98.8,111.88 98.61,112.07 98.41,112.07 v1(98.31,111.97)
  L3_IN1 w0.084: v1(89.26,124.51) 89.1,124.35 89.1,123.39 90.06,122.43 93.42,122.43 94.55,121.3 94.55,120.96 94.2,120.61 94.2,120.48 94.32,120.35 94.45,120.35 94.74,120.64 95.09,120.64 95.37,120.36 95.37,120.02 95.08,119.73 95.08,119.6 95.2,119.47 95.33,119.47 95.68,119.82 96.03,119.82 96.31,119.54 96.31,119.2 95.96,118.85 95.96,118.72 96.08,118.59 96.21,118.59 96.56,118.94 96.91,118.94 97.19,118.66 97.19,118.32 96.84,117.96 96.84,117.84 96.97,117.71 97.09,117.71 97.44,118.06 97.79,118.06 98.07,117.78 98.07,117.43 97.72,117.08 97.72,116.96 97.85,116.83 97.97,116.83 98.32,117.18 98.67,117.18 99.09,116.76 99.09,112.49 98.77,112.17 98.52,112.17 98.32,111.97 v1(98.31,111.97)
CSI2_DN2: length 32.9
  TOP w0.091: v1(95.94,111.97) 96.16,111.97 96.4,111.73 96.4,111.29 96.33,111.22 J2.10 ; v1(81.87,124.53) 81.69,124.71 81.69,125.21 81.8,125.32 U36.10 U36.1 81.8,127.09 81.68,127.2 81.68,127.32 82.58,128.22 82.58,128.71 82.85,128.97 J13.B13
  L3_IN1 w0.084: v1(95.94,111.97) 95.94,111.97 96.16,112.18 96.39,112.18 96.67,112.46 96.67,113.72 86.75,123.64 85.58,123.64 85.49,123.73 85.49,124.4 85.25,124.64 84.85,124.64 84.6,124.4 84.6,123.73 84.51,123.64 84.34,123.64 84.25,123.73 84.25,124.4 84,124.64 83.6,124.64 83.36,124.4 83.36,123.73 83.27,123.64 81.91,123.64 81.71,123.84 81.71,124.37 v1(81.87,124.53)
CSI2_DN3: length 32.8
  TOP w0.091: v1(80.34,124.52) 80.3,124.56 U36.7 U36.4 80.3,127 80.19,127.1 80.19,128.52 80.45,128.78 J13.B16 ; J2.4 95.13,111.22 95.2,111.29 95.2,111.84 94.97,112.06 v1(94.75,112.06)
  L3_IN1 w0.084: v1(80.34,124.52) 80.16,124.34 80.16,122.83 80.83,122.16 86.87,122.16 88.64,120.4 88.64,120.05 88.49,119.91 88.49,119.78 88.62,119.66 88.74,119.66 88.89,119.8 89.23,119.8 89.52,119.52 89.52,119.17 89.37,119.03 89.37,118.9 89.5,118.78 89.62,118.78 89.77,118.92 90.11,118.92 90.4,118.64 90.4,118.29 90.25,118.15 90.25,118.02 90.38,117.9 90.51,117.9 90.65,118.04 91,118.04 91.28,117.76 91.28,117.41 91.13,117.27 91.13,117.14 91.26,117.02 91.39,117.02 91.53,117.16 91.88,117.16 95.5,113.54 95.5,112.51 95.25,112.25 94.94,112.25 v1(94.75,112.06)
CSI2_DP0: length 32.9
  TOP w0.091: J2.30 100.33,111.22 100.27,111.29 100.27,111.84 99.55,112.55 v1(99.53,112.55) ; v1(90.16,124.48) 90.31,124.63 90.31,125.22 90.21,125.33 U35.9 U35.2 90.21,127.45 91.12,128.36 91.12,128.68 90.85,128.94 J13.B3
  L3_IN1 w0.084: v1(90.16,124.48) 90.28,124.36 90.28,123.51 90.56,123.23 95.28,123.23 95.88,122.63 95.88,122.24 95.61,121.98 95.61,121.63 95.9,121.35 96.24,121.35 96.64,121.75 96.76,121.75 96.89,121.62 96.89,121.49 96.49,121.1 96.49,120.75 96.78,120.47 97.12,120.47 97.52,120.87 97.64,120.87 97.77,120.74 97.77,120.61 97.38,120.22 97.38,119.87 97.66,119.59 98,119.59 98.4,119.98 98.53,119.98 98.65,119.86 98.65,119.73 98.26,119.34 98.26,118.99 98.54,118.71 98.88,118.71 99.22,119.04 99.47,119.04 99.96,118.55 99.96,112.49 99.87,112.4 99.69,112.4 v1(99.53,112.55)
CSI2_DP1: length 32.8
  TOP w0.091: v1(98.31,112.56) 98.53,112.34 98.72,112.34 99.07,112 99.07,111.29 99.13,111.22 J2.24 ; v1(88.68,124.51) 88.82,124.65 88.82,124.95 88.71,125.07 U35.6 U35.5 88.71,127.04 88.82,127.15 88.82,127.75 88.72,127.85 88.72,128.71 88.45,128.97 J13.B6
  L3_IN1 w0.084: v1(98.31,112.56) 98.43,112.44 98.66,112.44 98.82,112.6 98.82,116.65 98.56,116.92 98.43,116.92 98.08,116.57 97.74,116.57 97.45,116.85 97.45,117.19 97.8,117.55 97.8,117.67 97.68,117.8 97.55,117.8 97.2,117.45 96.85,117.45 96.57,117.73 96.57,118.08 96.92,118.43 96.92,118.55 96.8,118.68 96.67,118.68 96.32,118.33 95.97,118.33 95.69,118.61 95.69,118.96 96.04,119.31 96.04,119.43 95.92,119.56 95.79,119.56 95.44,119.21 95.09,119.21 94.81,119.49 94.81,119.84 95.1,120.13 95.1,120.25 94.97,120.38 94.85,120.38 94.56,120.09 94.21,120.09 93.93,120.37 93.93,120.72 94.28,121.07 94.28,121.19 93.31,122.16 89.95,122.16 88.84,123.27 88.84,124.35 v1(88.68,124.51)
CSI2_DP2: length 33
  TOP w0.091: v1(95.93,112.55) 95.93,112.55 95.96,112.55 96.67,111.84 96.67,111.29 96.73,111.22 J2.12 ; v1(81.29,124.53) 81.42,124.67 81.42,125.2 81.3,125.33 U36.9 U36.2 81.3,127.09 81.41,127.2 81.41,127.43 82.3,128.32 82.3,128.72 82.05,128.97 J13.B14
  L3_IN1 w0.084: v1(95.93,112.55) 96.03,112.45 96.28,112.45 96.41,112.57 96.41,113.6 86.64,123.38 85.47,123.38 85.23,123.62 85.23,124.29 85.14,124.38 84.96,124.38 84.87,124.29 84.87,123.62 84.63,123.38 84.23,123.38 83.98,123.62 83.98,124.29 83.89,124.38 83.71,124.38 83.63,124.29 83.63,123.62 83.38,123.38 81.8,123.38 81.45,123.73 81.45,124.37 v1(81.29,124.53)
CSI2_DP3: length 32.9
  TOP w0.091: J13.B17 79.65,128.78 79.89,128.54 79.89,127.14 79.8,127.04 U36.5 U36.6 79.8,125.21 79.89,125.11 79.89,124.67 79.75,124.54 v1(79.75,124.52) ; J2.6 95.53,111.22 95.47,111.29 95.47,111.95 94.78,112.64 v1(94.78,112.65)
  L3_IN1 w0.084: v1(79.75,124.52) 79.9,124.38 79.9,122.72 80.72,121.9 86.76,121.9 88.37,120.29 88.37,120.16 88.23,120.02 88.23,119.67 88.51,119.39 88.85,119.39 89,119.53 89.12,119.53 89.25,119.41 89.25,119.28 89.11,119.14 89.11,118.79 89.39,118.51 89.74,118.51 89.88,118.65 90,118.65 90.13,118.53 90.13,118.4 89.99,118.26 89.99,117.91 90.27,117.63 90.62,117.63 90.76,117.77 90.89,117.77 91.01,117.65 91.01,117.52 90.87,117.38 90.87,117.03 91.15,116.75 91.5,116.75 91.64,116.89 91.77,116.89 95.23,113.43 95.23,112.62 95.14,112.53 94.9,112.53 v1(94.78,112.65)
CSI2_I2C_SCL: length 3.4
  TOP w0.102: R164.1 84.45,126.61 J13.B11
CSI2_I2C_SDA: length 3.4
  TOP w0.102: J13.B10 85.25,126.53 R161.1
CSI2_MCLK: length 3.6
  TOP w0.102: J13.B8 86.85,127.08 R26.1
CSI2_NRST: length 3.5
  TOP w0.102: R303.1 86.05,126.82 J13.B9
CSI2_SYNC: length 45.2
  TOP w0.102: v1(76.73,113.7) 76.73,113.51 77.09,113.15 J1.32
  L6_IN2 w0.114: v1(75.08,139.29) 75.15,139.23 75.15,115.55 76.73,113.98 v1(76.73,113.7)
  BOTTOM w0.109: v1(75.08,139.29) 82.74,139.29 84.71,137.33 R25.1 84.81,135.38 85.39,134.8 85.39,132.87 R163.1
CSI_MCLK: length 50.1
  TOP w0.102: v1(63.18,124.04) 62.86,124.37 J12.B8 ; v1(72.17,112.35) 72.45,112.35 72.94,111.87 72.94,111.16 73.09,111.01 J1.12 ; R26.2 86.87,125.05 v1(86.72,125.05)
  L6_IN2 w0.114: v1(63.18,124.04) 63.33,124.04 63.74,123.63 63.74,120.66 72.05,112.35 v1(72.17,112.35)
  BOTTOM w0.109: v1(86.72,125.05) 86.72,125.24 85.97,125.99 64.19,125.99 63.18,124.98 v1(63.18,124.04)
CSI_NRST: length 55.7
  TOP w0.102: v1(74.32,106.22) 74.32,106.4 74.69,106.77 J1.19 ; J12.B9 62.06,124.56 v1(63.19,123.42) ; v1(86.14,125.07) 86.14,125.39 R303.2
  L6_IN2 w0.114: v1(63.19,123.42) 63.19,120.49 71.24,112.44 71.24,109.1 74.12,106.22 v1(74.32,106.22)
  BOTTOM w0.109: v1(86.14,125.07) 85.62,125.59 64.19,125.59 63.71,125.11 63.71,123.94 v1(63.19,123.42)
CSI_PWDN: length 74.5
  TOP w0.102: J2.71 108.73,106.15 107.04,104.46 93.96,104.46 v1(93.34,105.08) ; R165.1 82.59,125.69 82.45,125.82 82.45,127.19 82.77,127.5 v1(82.77,127.62) ; J12.A11 v1(60.06,133.56)
  L6_IN2 w0.114: v1(93.34,105.08) 93.34,115.25 82.77,125.82 v1(82.77,127.62)
  BOTTOM w0.109: v1(60.06,133.56) 62.9,130.71 80.75,130.71 82.77,128.7 v1(82.77,127.62)
CSI_SYNC1: length 3.7
  TOP w0.33: J12.A10 v1(60.86,133.62)
  BOTTOM w0.305: v1(60.86,133.62) 61.34,134.11 R29.1 60.29,134.72 R28.2
CSI_SYNC2: length 30.7
  TOP w0.33: J13.A10 v1(84.85,133.56)
  BOTTOM w0.102: v1(84.85,133.56) 84.85,134.49 R25.2
  BOTTOM w0.109: R29.2 61.34,136.62 63.43,138.71 82.42,138.71 84.16,136.98 84.16,134.95 84.48,134.63 R25.2
DCDC_5V: length 7.9
  TOP w0.381: TP67.1 v1(179.05,112.14)
  BOTTOM w0.254: U63.5 45.91,64.54 v1(46.15,64.79)
  BOTTOM w0.381: R267.1 46.08,105.18 46.08,103.16
  vias: v1(25.62,60.47) v1(25.62,59.76) v1(26.25,60.46) v1(49.3,54.7) v1(49.59,61.45) v1(49.95,54.7) v1(50.24,61.45) v1(50.58,54.69) v1(50.87,61.44) v1(52.02,98.73) v1(52.02,97.69) v1(52.67,98.74) v1(52.67,97.7) v1(53.3,98.72) v1(53.3,97.68) v1(57.06,20.86) v1(57.16,22.85) v1(57.88,20.82) v1(59.77,36.84) v1(61.09,36.85) v1(61.75,36.85) v1(62.37,36.84) v1(82.09,61.69) v1(82.09,60.88) v1(82.74,61.7) v1(82.74,60.89) v1(83.37,61.68) v1(83.37,60.87) v1(174.32,136.51) v1(174.35,135.67) v1(174.35,134.76)
DCDC_5V_CN: length 24.1
  TOP w0.203: TP125.1 172.66,123.63 R185.2
  TOP w0.381: C171.1 171.46,128.6 171.66,128.79 171.66,134.83 171.28,135.21 170.2,135.21 170,135.41 C158.1 170,137.27 U71.2 169.19,137.28 168.81,137.66 168.81,139.84 169.19,140.23 R1.1 ; C171.1 169.88,128.6 C170.1 169.89,128.58 U48.8 ; C171.1 170.98,127.83 171.36,127.45 172.29,127.45 172.67,127.07 R179.1 172.66,126.77 R180.1 172.66,125.67 R185.2
DEBUG_ACCESS: length 3
  TOP w0.109: U11.9 30.68,19.12 TP18.1
DEBUG_ACCESS1: length 2
  TOP w0.203: U17.9 43.62,29.27 TP27.1
DSI_BL_PWM: length 50
  TOP w0.102: v1(75.2,106.34) 75.22,106.36 75.39,106.36 75.49,106.46 J1.23 ; R305.2 v1(38.89,124.94)
  L6_IN2 w0.114: v1(70.56,114.71) 71.41,113.85 73,113.85 75.08,111.78 75.08,106.54 75.2,106.41 v1(75.2,106.34)
  BOTTOM w0.109: v1(38.89,124.94) 38.89,123.81 47.61,115.09 70.17,115.09 v1(70.56,114.71)
DSI_CKN: length 82.5
  TOP w0.091: v1(88.32,105.64) 88.28,105.64 87.56,106.36 87.56,106.9 87.49,106.97 J1.83 ; v1(45.73,120.69) 45.94,120.9 45.94,125.21 45.82,125.33 U38.1 U38.10 45.82,126.84 45.94,126.96 45.94,133.02 44.95,134 44.09,134 43.96,133.88 43.96,133.69 43.87,133.6 43.61,133.6 43.52,133.69 43.52,133.92 43.44,134 43.18,134 42.91,133.73 42.91,133.33 43.26,132.98 J14.A2
  L3_IN1 w0.084: v1(45.73,120.69) 45.96,120.92 45.96,122.16 46.31,122.51 47.32,122.51 49.13,120.7 49.26,120.7 49.45,120.89 49.79,120.89 50.07,120.6 50.07,120.26 49.88,120.07 49.88,119.94 50.01,119.81 50.14,119.81 50.33,120 50.67,120 50.96,119.72 50.96,119.38 50.76,119.19 50.76,119.06 50.89,118.93 51.02,118.93 51.21,119.12 51.55,119.12 51.84,118.84 51.84,118.49 51.65,118.3 51.65,118.18 51.77,118.05 51.9,118.05 52.09,118.24 52.43,118.24 52.72,117.96 52.72,117.61 52.53,117.42 52.53,117.3 52.65,117.17 52.78,117.17 52.97,117.36 53.31,117.36 53.6,117.08 53.6,116.73 53.41,116.54 53.41,116.42 53.53,116.29 53.66,116.29 53.85,116.48 54.19,116.48 54.48,116.2 54.48,115.85 54.29,115.66 54.29,115.54 54.41,115.41 54.54,115.41 54.73,115.6 55.08,115.6 55.36,115.32 55.36,114.97 55.17,114.78 55.17,114.66 55.29,114.53 55.42,114.53 55.61,114.72 55.96,114.72 56.24,114.44 56.24,114.09 56.05,113.9 56.05,113.78 56.17,113.65 56.3,113.65 56.49,113.84 56.84,113.84 57.12,113.56 57.12,113.21 56.93,113.02 56.93,112.9 66.24,103.59 87.86,103.59 88.8,104.53 88.8,105.77 88.73,105.84 88.52,105.84 v1(88.32,105.64)
DSI_CKP: length 82.4
  TOP w0.091: J1.85 87.89,106.96 87.83,106.9 87.83,106.5 88.11,106.22 v1(88.3,106.22) ; J14.A3 42.46,132.89 42.65,133.08 42.65,133.84 43.09,134.28 45.05,134.28 46.2,133.13 46.2,126.96 46.32,126.85 U38.9 U38.2 46.32,125.32 46.2,125.21 46.2,120.88 46.31,120.77 v1(46.31,120.69)
  L3_IN1 w0.084: v1(46.31,120.69) 46.31,120.75 46.22,120.84 46.22,122.04 46.42,122.24 47.21,122.24 49.02,120.43 49.37,120.43 49.56,120.62 49.68,120.62 49.81,120.49 49.81,120.37 49.62,120.18 49.62,119.83 49.9,119.55 50.25,119.55 50.44,119.74 50.56,119.74 50.69,119.61 50.69,119.49 50.5,119.3 50.5,118.95 50.78,118.67 51.13,118.67 51.32,118.86 51.44,118.86 51.57,118.73 51.57,118.61 51.38,118.42 51.38,118.07 51.66,117.79 52.01,117.79 52.2,117.98 52.32,117.98 52.45,117.85 52.45,117.72 52.26,117.53 52.26,117.19 52.54,116.91 52.89,116.91 53.08,117.1 53.2,117.1 53.33,116.97 53.33,116.84 53.14,116.65 53.14,116.31 53.42,116.03 53.77,116.03 53.96,116.22 54.08,116.22 54.21,116.09 54.21,115.96 54.02,115.77 54.02,115.43 54.3,115.14 54.65,115.14 54.84,115.33 54.97,115.33 55.09,115.21 55.09,115.08 54.9,114.89 54.9,114.55 55.18,114.26 55.53,114.26 55.72,114.45 55.85,114.45 55.97,114.33 55.97,114.2 55.78,114.01 55.78,113.67 56.06,113.38 56.41,113.38 56.6,113.57 56.73,113.57 56.85,113.45 56.85,113.32 56.66,113.13 56.66,112.79 66.13,103.32 87.97,103.32 89.07,104.42 89.07,105.88 88.84,106.11 88.42,106.11 v1(88.3,106.22)
DSI_DN0: length 80.6
  TOP w0.091: v1(85.89,105.64) 85.88,105.64 85.84,105.64 85.16,106.32 85.16,106.9 85.09,106.97 J1.71 ; J14.B2 43.66,129.24 43.4,128.98 43.4,128.19 42.78,127.57 42.78,127.18 42.87,127.09 U37.1 U37.10 42.87,125.14 42.79,125.06 42.79,124.72 v1(42.96,124.55)
  L3_IN1 w0.084: v1(42.96,124.55) 42.8,124.71 42.8,125.06 43.13,125.4 47.31,125.4 51.3,121.4 51.65,121.4 52.08,121.84 52.21,121.84 52.33,121.71 52.33,121.59 51.9,121.15 51.9,120.81 52.18,120.52 52.53,120.52 53.02,121.01 53.14,121.01 53.27,120.89 53.27,120.76 52.78,120.27 52.78,119.92 53.06,119.64 53.41,119.64 53.9,120.13 54.02,120.13 54.15,120.01 54.15,119.88 53.66,119.39 53.66,119.04 53.94,118.76 54.29,118.76 54.78,119.25 54.9,119.25 55.03,119.12 55.03,119 54.54,118.51 54.54,118.16 54.82,117.88 55.17,117.88 55.66,118.37 55.78,118.37 55.91,118.24 55.91,118.12 55.42,117.63 55.42,117.28 55.7,117 56.05,117 56.54,117.49 56.67,117.49 56.79,117.36 56.79,117.24 56.3,116.75 56.3,116.4 56.58,116.12 56.93,116.12 57.42,116.61 57.55,116.61 57.67,116.48 57.67,116.36 57.18,115.87 57.18,115.52 57.47,115.24 57.81,115.24 58.3,115.73 58.43,115.73 58.55,115.6 58.55,115.48 58.06,114.99 58.06,114.64 58.35,114.36 58.69,114.36 59.18,114.85 59.31,114.85 59.43,114.72 59.43,114.6 58.94,114.11 58.94,113.76 59.23,113.48 59.57,113.48 60.06,113.97 60.19,113.97 60.31,113.84 60.31,113.72 59.83,113.23 59.83,112.88 60.11,112.6 60.45,112.6 60.94,113.09 61.07,113.09 61.19,112.96 61.19,112.83 60.71,112.35 60.71,112 65.93,106.77 69.08,106.77 70.91,108.6 84.35,108.6 85.16,107.78 85.16,106.04 85.44,105.76 85.77,105.76 v1(85.89,105.64)
DSI_DN1: length 80.4
  TOP w0.091: J14.B5 41.26,129.03 40.91,128.68 40.91,128.3 41.13,128.08 41.13,127.07 41.36,126.84 U37.4 U37.7 41.36,125.33 41.13,125.1 41.13,124.77 41.37,124.53 v1(41.37,124.49) ; v1(87.13,105.64) 86.96,105.47 86.71,105.47 86.58,105.61 86.58,106.19 86.36,106.4 86.36,107 86.29,107.07 J1.77
  L3_IN1 w0.084: v1(41.37,124.49) 41.37,124.48 41.05,124.16 41.05,123.73 41.16,123.62 43.52,123.62 43.76,123.38 43.76,122.85 43.88,122.74 44,122.74 44.12,122.85 44.12,123.38 44.36,123.62 48.25,123.62 58.8,113.07 58.8,112.73 58.65,112.58 58.65,112.45 58.78,112.32 58.9,112.32 59.05,112.47 59.4,112.47 59.68,112.19 59.68,111.85 59.53,111.69 59.53,111.57 59.66,111.44 59.78,111.44 59.93,111.59 60.28,111.59 60.56,111.31 60.56,110.97 60.41,110.81 60.41,110.69 60.54,110.56 60.66,110.56 60.81,110.71 61.16,110.71 61.44,110.43 61.44,110.08 61.29,109.93 61.29,109.81 61.42,109.68 61.54,109.68 61.69,109.83 62.04,109.83 62.32,109.55 62.32,109.2 62.17,109.05 62.17,108.93 62.3,108.8 62.42,108.8 62.57,108.95 62.92,108.95 63.2,108.67 63.2,108.32 63.05,108.17 63.05,108.05 63.18,107.92 63.3,107.92 63.46,108.07 63.8,108.07 64.08,107.79 64.08,107.44 63.93,107.29 63.93,107.17 64.06,107.04 64.18,107.04 64.34,107.19 64.68,107.19 64.96,106.91 64.96,106.56 64.81,106.41 64.81,106.29 64.94,106.16 65.07,106.16 65.22,106.31 65.56,106.31 65.85,106.03 65.85,105.68 65.69,105.53 65.69,105.4 65.82,105.28 65.95,105.28 66.1,105.43 66.44,105.43 67.45,104.42 68.89,104.42 68.98,104.51 68.98,105.39 69.23,105.64 69.62,105.64 69.87,105.39 69.87,104.51 69.96,104.42 70.14,104.42 70.22,104.51 70.22,105.65 70.47,105.9 70.87,105.9 71.11,105.65 71.11,104.51 71.2,104.42 71.38,104.42 71.47,104.51 71.47,105.65 71.71,105.9 72.11,105.9 72.36,105.65 72.36,104.51 72.45,104.42 87.2,104.42 87.62,104.83 87.62,105.63 87.48,105.76 87.25,105.76 v1(87.13,105.64)
DSI_DN2: length 80.4
  TOP w0.091: J14.B13 34.86,129.05 34.62,128.81 34.62,128.44 33.61,127.43 U39.1 U39.10 33.61,125.33 33.38,125.09 33.38,124.74 33.61,124.51 v1(33.61,124.44) ; v1(89.49,105.64) 89.49,105.58 89.32,105.41 89.16,105.41 89.05,105.53 89.05,106.09 88.76,106.38 88.76,106.9 88.69,106.97 J1.89
  L3_IN1 w0.084: v1(33.61,124.44) 33.59,124.44 33.4,124.26 33.4,123.56 36.75,120.21 39.84,120.21 39.93,120.3 39.93,120.81 40.17,121.05 40.57,121.05 40.82,120.81 40.82,120.3 40.91,120.21 41.08,120.21 41.17,120.3 41.17,120.9 41.42,121.15 41.82,121.15 42.06,120.9 42.06,120.3 42.15,120.21 48.26,120.21 65.63,102.84 88.47,102.84 90.01,104.38 90.01,105.69 89.88,105.81 89.67,105.81 v1(89.49,105.64)
DSI_DN3: length 80.5
  TOP w0.091: v1(32.11,124.47) 31.95,124.63 31.95,125.04 32.11,125.2 U39.7 U39.4 32.11,126.8 31.88,127.04 31.88,127.57 32.15,127.85 32.15,128.69 32.46,129 J14.B16 ; J1.95 89.89,106.97 89.96,106.9 89.96,106.43 90.25,106.13 90.25,105.53 90.39,105.39 90.51,105.39 90.71,105.59 v1(90.71,105.64)
  L3_IN1 w0.084: v1(90.71,105.64) 90.84,105.77 91.11,105.77 91.19,105.68 91.19,104.52 88.65,101.98 65.16,101.98 47.8,119.35 36.3,119.35 31.95,123.7 31.95,124.31 v1(32.11,124.47)
DSI_DP0: length 80.6
  TOP w0.091: v1(85.9,106.22) 85.64,106.22 85.43,106.43 85.43,106.9 85.49,106.96 J1.73 ; J14.B3 42.86,129.19 43.13,128.92 43.13,128.31 42.51,127.68 42.51,127.16 42.37,127.02 U37.2 U37.9 42.37,125.19 42.52,125.04 42.52,124.72 42.37,124.58 v1(42.37,124.55)
  L3_IN1 w0.084: v1(42.37,124.55) 42.53,124.71 42.53,125.17 43.02,125.66 47.42,125.66 51.41,121.67 51.54,121.67 51.97,122.1 52.32,122.1 52.6,121.82 52.6,121.48 52.17,121.04 52.17,120.92 52.29,120.79 52.42,120.79 52.91,121.28 53.25,121.28 53.54,121 53.54,120.65 53.05,120.16 53.05,120.04 53.17,119.91 53.3,119.91 53.79,120.4 54.13,120.4 54.42,120.12 54.42,119.77 53.93,119.28 53.93,119.15 54.05,119.03 54.18,119.03 54.67,119.52 55.01,119.52 55.3,119.23 55.3,118.89 54.81,118.4 54.81,118.27 54.93,118.15 55.06,118.15 55.55,118.64 55.9,118.64 56.18,118.35 56.18,118.01 55.69,117.52 55.69,117.39 55.81,117.27 55.94,117.27 56.43,117.76 56.78,117.76 57.06,117.47 57.06,117.13 56.57,116.64 56.57,116.51 56.7,116.39 56.82,116.39 57.31,116.88 57.66,116.88 57.94,116.59 57.94,116.25 57.45,115.76 57.45,115.63 57.58,115.51 57.7,115.51 58.19,116 58.54,116 58.82,115.71 58.82,115.37 58.33,114.88 58.33,114.75 58.46,114.63 58.58,114.63 59.07,115.11 59.42,115.11 59.7,114.83 59.7,114.49 59.21,114 59.21,113.87 59.34,113.74 59.46,113.74 59.95,114.23 60.3,114.23 60.58,113.95 60.58,113.6 60.09,113.12 60.09,112.99 60.22,112.86 60.34,112.86 60.83,113.35 61.18,113.35 61.46,113.07 61.46,112.72 60.97,112.23 60.97,112.11 66.04,107.04 68.97,107.04 70.79,108.86 84.46,108.86 85.43,107.9 85.43,106.17 85.57,106.03 85.71,106.03 v1(85.9,106.22)
DSI_DP1: length 80.3
  TOP w0.091: J14.B6 40.46,128.94 40.64,128.76 40.64,128.19 40.87,127.97 U37.5 U37.6 40.87,124.57 v1(40.79,124.49) ; J1.79 86.69,107.08 86.63,107.02 86.63,106.51 86.85,106.29 86.92,106.22 v1(87.12,106.22)
  L3_IN1 w0.084: v1(40.79,124.49) 40.79,123.62 41.05,123.35 43.41,123.35 43.5,123.26 43.5,122.74 43.77,122.47 44.11,122.47 44.39,122.74 44.39,123.26 44.47,123.35 48.14,123.35 58.53,112.96 58.53,112.84 58.38,112.69 58.38,112.34 58.67,112.06 59.01,112.06 59.16,112.21 59.29,112.21 59.41,112.08 59.41,111.96 59.26,111.81 59.26,111.46 59.55,111.18 59.89,111.18 60.04,111.33 60.17,111.33 60.3,111.2 60.3,111.08 60.14,110.92 60.14,110.58 60.43,110.3 60.77,110.3 60.92,110.45 61.05,110.45 61.18,110.32 61.18,110.2 61.02,110.04 61.02,109.7 61.31,109.41 61.65,109.41 61.8,109.57 61.93,109.57 62.06,109.44 62.06,109.31 61.9,109.16 61.9,108.82 62.19,108.53 62.53,108.53 62.69,108.69 62.81,108.69 62.94,108.56 62.94,108.43 62.79,108.28 62.79,107.94 63.07,107.65 63.41,107.65 63.57,107.8 63.69,107.8 63.82,107.68 63.82,107.55 63.67,107.4 63.67,107.06 63.95,106.77 64.3,106.77 64.45,106.92 64.57,106.92 64.7,106.8 64.7,106.67 64.55,106.52 64.55,106.18 64.83,105.89 65.18,105.89 65.33,106.04 65.45,106.04 65.58,105.92 65.58,105.79 65.43,105.64 65.43,105.29 65.71,105.01 66.06,105.01 66.21,105.16 66.33,105.16 67.34,104.15 69,104.15 69.25,104.4 69.25,105.28 69.34,105.37 69.51,105.37 69.6,105.28 69.6,104.4 69.85,104.15 70.25,104.15 70.49,104.4 70.49,105.54 70.58,105.63 70.76,105.63 70.85,105.54 70.85,104.4 71.09,104.15 71.49,104.15 71.74,104.4 71.74,105.54 71.83,105.63 72,105.63 72.09,105.54 72.09,104.4 72.34,104.15 87.31,104.15 87.88,104.72 87.88,105.82 87.67,106.03 87.31,106.03 v1(87.12,106.22)
DSI_DP2: length 80.5
  TOP w0.091: J1.91 89.09,106.96 89.03,106.9 89.03,106.49 89.29,106.22 v1(89.48,106.22) ; v1(33.02,124.44) 33.11,124.53 U39.9 U39.2 33.11,126.82 33.34,127.06 33.34,127.54 34.36,128.55 34.36,128.74 34.06,129.04 J14.B14
  L3_IN1 w0.084: v1(33.02,124.44) 33.02,124.41 33.13,124.29 33.13,123.45 36.64,119.94 39.95,119.94 40.19,120.19 40.19,120.7 40.28,120.79 40.46,120.79 40.55,120.7 40.55,120.19 40.8,119.94 41.19,119.94 41.44,120.19 41.44,120.79 41.53,120.88 41.71,120.88 41.79,120.79 41.79,120.19 42.04,119.94 48.15,119.94 65.52,102.58 88.58,102.58 90.27,104.27 90.27,105.8 89.99,106.08 89.62,106.08 v1(89.48,106.22)
